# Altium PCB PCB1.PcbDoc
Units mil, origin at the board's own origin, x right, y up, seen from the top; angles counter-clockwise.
Board outline 2600 x 2600 mil, 2 copper layers (Top Layer, Bottom Layer); 21 components, 109 nets, 295 pads, 0 vias.
Unrouted connection lines stored in the file: 152.
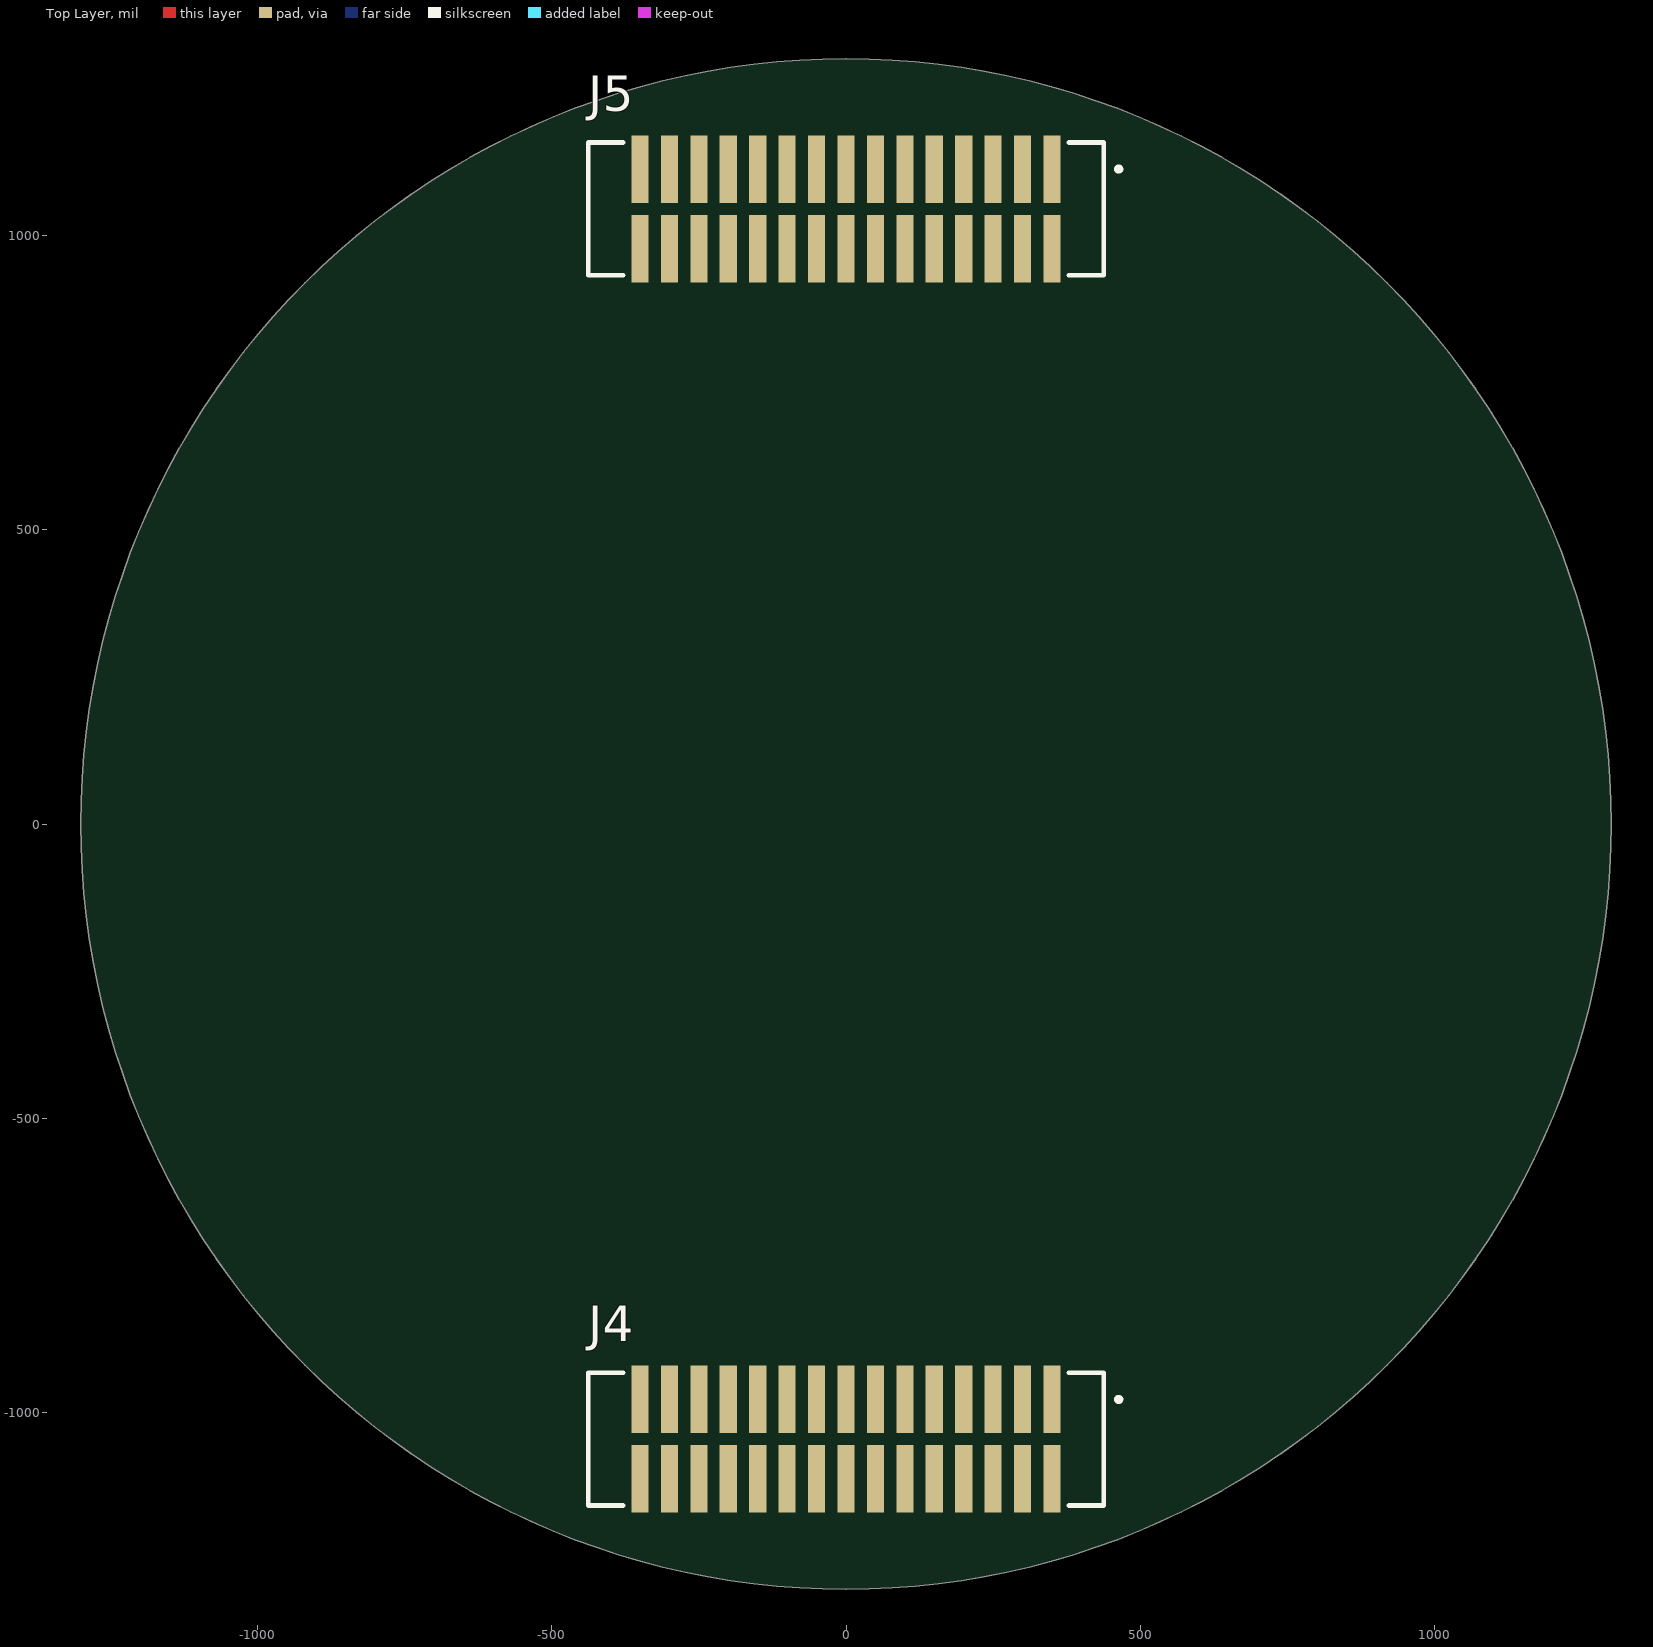
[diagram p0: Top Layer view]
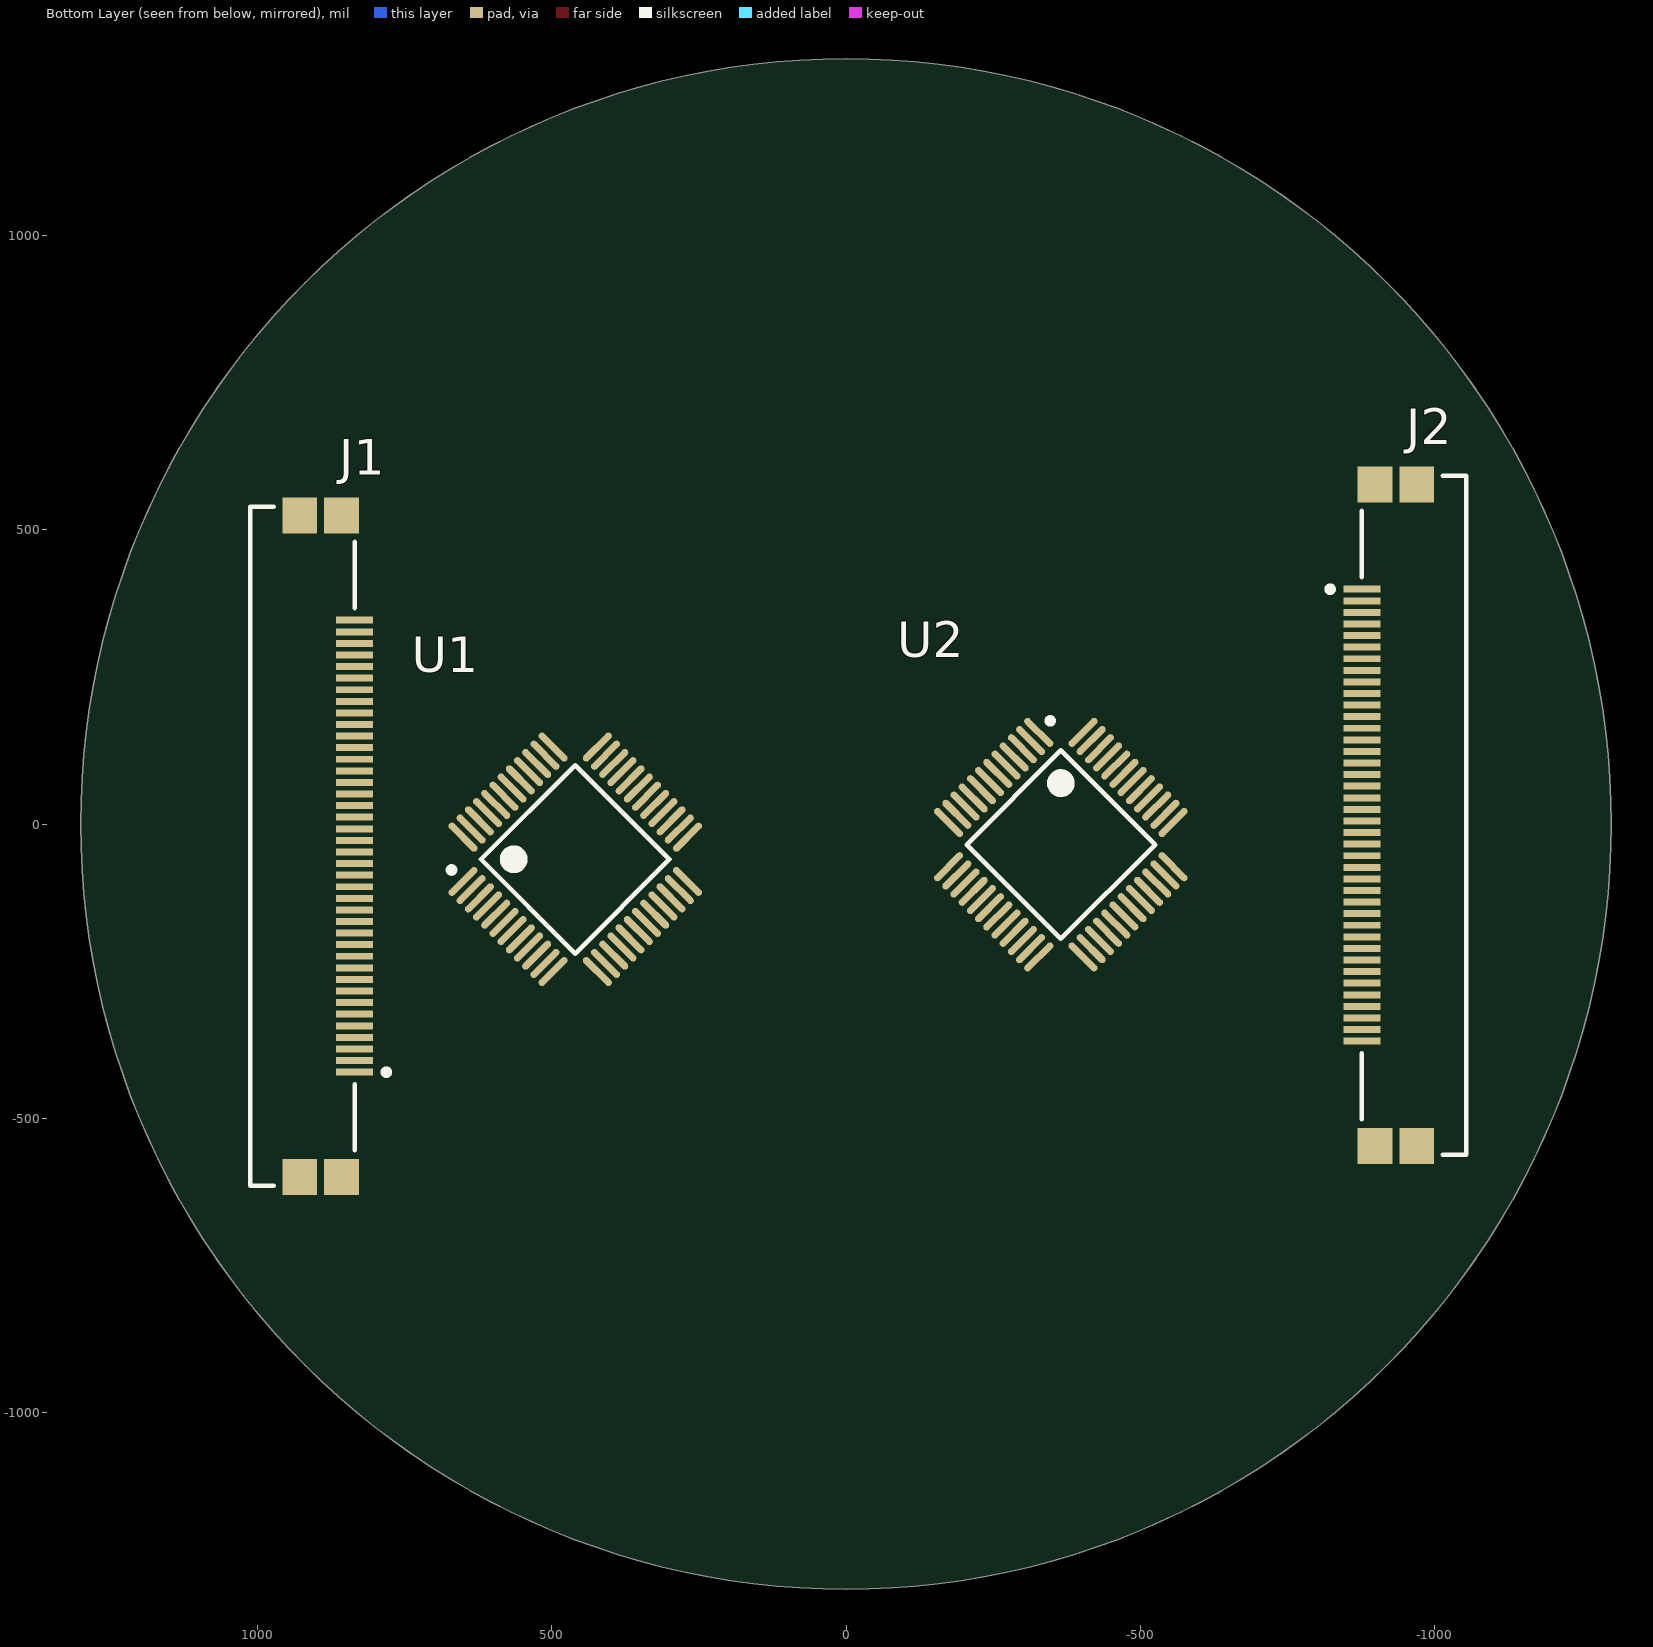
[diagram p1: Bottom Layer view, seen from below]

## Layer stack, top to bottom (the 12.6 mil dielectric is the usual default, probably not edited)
Top Solder: solder mask 0.4, Solder Resist, Dk 3.5
Top Layer: signal copper 1.4
Dielectric 1: dielectric 12.6, FR-4, Dk 4.8
Bottom Layer: signal copper 1.4
Bottom Solder: solder mask 0.4, Solder Resist, Dk 3.5

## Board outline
-1300,0 ccw(c0,0) 0,-1300 ccw(c0,0) 1300,0 ccw(c0,0) 0,1300 ccw(c0,0)

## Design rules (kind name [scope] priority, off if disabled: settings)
Clearance [All] p1: gap=8 ignorepadtopadclearanceinfootprint=FALSE except(6: Arc-SMDPad Track-SMDPad SMDPad-SMDPad; 12: Arc-Via Track-Via)
HoleSize [All] p1: absolutevalues=TRUE maxlimit=100 minlimit=14 maxpercent=80.000 minpercent=20.000
PolygonConnect [All] p1: connectstyle=Relief reliefconductorwidth=10 reliefentries=4 polygonreliefangle="90 Angle" airgapwidth=10
RoutingVias [All] p1: holewidth=14 width=28 viastyle="Through Hole" minholewidth=14 minwidth=28 maxholewidth=14 maxwidth=28
SolderMaskExpansion [All] p1: expansion=4 istentingtop=FALSE
Width [All] p1: maxlimit=30 minlimit=10 preferedwidth=10
29 further rules are at their usual default settings.

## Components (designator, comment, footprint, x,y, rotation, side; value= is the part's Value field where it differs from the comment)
C1 "330nF" FP-CC0805-0_85-MFG 4445,5125 r0 top value="330 nF"
C2 "33nF" CAPC2013X95X45NL10T25 4260,5135 r0 top
C3 "3.3nF" FP-C0805C-DN-MFG 4085,5125 r0 top value="3,300 pF"
C4 "330pF" FP-C0805C-DN-MFG 3915,5125 r0 top value="330 pF"
C5 "100 nF" FP-C0805C-DN-MFG 3575,5125 r0 top value="0.10 μF"
C6 "100 nF" FP-C0805C-DN-MFG 3035,5125 r0 top value="0.10 μF"
C7 "100 nF" FP-C0805C-DN-MFG 2865,5125 r0 top value="0.10 μF"
J1 "200485-0540" FP-200485-0540-MFG 923.39,-37.68 r270 bottom
J2 "200485-0540" FP-200485-0540-MFG -965,15 r90 bottom
J3 "5600200620" FP-5600200620-MFG 4820,5010 r90 top
J4 "TFM-115-02-L-D" SAMTEC_TFM-115-02-L-D 0,-1045 r180 top
J5 "TFM-115-02-L-D" SAMTEC_TFM-115-02-L-D 0,1045 r180 top
P1 "61300311021" 61300311021 1735,5020 r0 top
P2 "61300211021" 61300211021 2065,5020 r0 top
P3 "61300211021" 61300211021 2345,5020 r0 top
R1 "100" RESC2013X50X30LL20T20 5535,5140 r0 top
R2 "1k" RESC2013X55X40LL15T20 3740,5140 r0 top
S1 "SSSS212400" SSSS212400 2670,4675 r90 top
U1 "ADG732BSUZ-REEL" ADI-SU-48_N 460,-60 r135 bottom
U2 "ADG732BSUZ-REEL" ADI-SU-48_N -365,-35 r225 bottom
U3 "OPA2388IDR" FP-D0008A-IPC_B 3315,5060 r0 top

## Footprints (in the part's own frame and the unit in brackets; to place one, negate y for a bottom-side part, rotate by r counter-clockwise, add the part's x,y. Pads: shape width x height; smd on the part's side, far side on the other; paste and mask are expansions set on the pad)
61300211021 [mm] "Pin Header, pitch 2.54 mm, THT, Angled, single row, 2p"
  rect 1.65x1.65 hole 1.1: 1(1.27,2.77)
  round 1.65 hole 1.1: 2(-1.27,2.77)
  silkscreen extent -2.69,-7.27 2.69,1.35, body extent -2.54,-7.27 2.54,3.09, height 2.58
61300311021 [mm] "Pin Header, pitch 2.54 mm, THT, Angled, single row, 3p"
  rect 1.65x1.65 hole 1.1: 1(2.54,2.77)
  round 1.65 hole 1.1: 2(0,2.77) 3(-2.54,2.77)
  silkscreen extent -3.96,-7.27 3.96,1.35, body extent -3.81,-7.27 3.81,3.09, height 2.58
ADI-SU-48_N [mm] "QFP, 48-Leads, Body 7x7mm, Pitch 0.5mm, IPC Medium Density"
  oval 1.65x0.3 smd: 1(-4.1,2.75) 2(-4.1,2.25) 3(-4.1,1.75) 4(-4.1,1.25) 5(-4.1,0.75) 6(-4.1,0.25) 7(-4.1,-0.25) 8(-4.1,-0.75) 9(-4.1,-1.25) 10(-4.1,-1.75) 11(-4.1,-2.25) 12(-4.1,-2.75) 25(4.1,-2.75) 26(4.1,-2.25) 27(4.1,-1.75) 28(4.1,-1.25) 29(4.1,-0.75) 30(4.1,-0.25) 31(4.1,0.25) 32(4.1,0.75) 33(4.1,1.25) 34(4.1,1.75) 35(4.1,2.25) 36(4.1,2.75)
  oval 0.3x1.65 smd: 13(-2.75,-4.1) 14(-2.25,-4.1) 15(-1.75,-4.1) 16(-1.25,-4.1) 17(-0.75,-4.1) 18(-0.25,-4.1) 19(0.25,-4.1) 20(0.75,-4.1) 21(1.25,-4.1) 22(1.75,-4.1) 23(2.25,-4.1) 24(2.75,-4.1) 37(2.75,4.1) 38(2.25,4.1) 39(1.75,4.1) 40(1.25,4.1) 41(0.75,4.1) 42(0.25,4.1) 43(-0.25,4.1) 44(-0.75,4.1) 45(-1.25,4.1) 46(-1.75,4.1) 47(-2.25,4.1) 48(-2.75,4.1)
  silkscreen extent -4.22,-2.88 2.88,3.57, body extent -3.5,-3.5 3.5,3.5, height 1.2
CAPC2013X95X45NL10T25 [mm] "Chip Capacitor, 2-Leads, Body 2.00x1.25mm, IPC Medium Density"
  rect 1.2x1.4 smd: 1(-0.85,0) 2(0.85,0)
  body extent -1.05,-0.67 1.05,0.67, height 0.95
FP-200485-0540-MFG [mm]
  rect 0.3x1.6 smd paste-1000 mask+0: 1(9.75,2.245) 2(9.25,2.245) 3(8.75,2.245) 4(8.25,2.245) 5(7.75,2.245) 6(7.25,2.245) 7(6.75,2.245) 8(6.25,2.245) 9(5.75,2.245) 10(5.25,2.245) 11(4.75,2.245) 12(4.25,2.245) 13(3.75,2.245) 14(3.25,2.245) 15(2.75,2.245) 16(2.25,2.245) 17(1.75,2.245) 18(1.25,2.245) 19(0.75,2.245) 20(0.25,2.245) 21(-0.25,2.245) 22(-0.75,2.245) 23(-1.25,2.245) 24(-1.75,2.245) 25(-2.25,2.245) 26(-2.75,2.245) 27(-3.25,2.245) 28(-3.75,2.245) 29(-4.25,2.245) 30(-4.75,2.245) 31(-5.25,2.245) 32(-5.75,2.245) 33(-6.25,2.245) 34(-6.75,2.245) 35(-7.25,2.245) 36(-7.75,2.245) 37(-8.25,2.245) 38(-8.75,2.245) 39(-9.25,2.245) 40(-9.75,2.245)
  rect 1.55x1.5 smd paste+0 mask+0: 41(-14.275,1.685) 42(14.275,1.685) 43(-14.275,-0.115) 44(14.275,-0.115)
  silkscreen extent -14.65,-2.25 14.65,3.74, body extent -14.75,-2.2 14.74,2.8, height 5.7
FP-5600200620-MFG [mm]
  rect 1.2x2.2 smd paste+0 mask+0: 1(5,4.68) 2(3,4.68) 3(1,4.68) 4(-1,4.68) 5(-3,4.68) 6(-5,4.68)
  rect 2x4.2 smd paste+0 mask+0: 7(-8.6,-0.9) 8(8.6,-0.9)
  silkscreen extent -9.43,-4 9.43,6.63, body extent -9.7,-4.1 9.7,5.88, height 0.25
FP-C0805C-DN-MFG [mm]
  rect 0.95x1.35 smd paste+0 mask+0: 1(-0.75,0) 2(0.75,0)
  silkscreen extent -1.1,-1.07 1.1,1.07, body extent -1.4,-0.85 1.4,0.85, height 0.25
FP-CC0805-0_85-MFG [mm]
  rect 0.95x1.4 smd paste+0 mask+0: 1(-0.925,0) 2(0.925,0)
  silkscreen extent -0.08,-0.72 0.08,0.72, body extent -1.6,-1.05 1.6,1.05, height 0.25
FP-D0008A-IPC_B [mil]
  rect 85.4x22.92 smd paste+0 mask+0: 1(-93.06,75)
  rrect100% 85.4x22.92 smd paste+0 mask+0: 2(-93.06,25) 3(-93.06,-25) 4(-93.06,-75) 5(93.06,-75) 6(93.06,-25) 7(93.06,25) 8(93.06,75)
  silkscreen extent -162,-97 31,97, body extent -146,-106 146,106, height 10
RESC2013X50X30LL20T20 [mm] "Chip Resistor, 2-Leads, Body 2.00x1.25mm, IPC High Density"
  rect 0.85x1.35 smd: 1(-0.825,0) 2(0.825,0)
  silkscreen extent -0.1,-0.58 0.1,0.58, body extent -1.1,-0.72 1.1,0.72, height 0.5
RESC2013X55X40LL15T20 [mm] "Chip Resistor, 2-Leads, Body 2.00x1.25mm, IPC High Density"
  rect 0.9x1.3 smd: 1(-0.775,0) 2(0.775,0)
  body extent -1.07,-0.7 1.07,0.7, height 0.55
SAMTEC_TFM-115-02-L-D [mm]
  rect 0.74x2.92 smd: 01(-8.89,-1.715) 02(-8.89,1.715) 03(-7.62,-1.715) 04(-7.62,1.715) 05(-6.35,-1.715) 06(-6.35,1.715) 07(-5.08,-1.715) 08(-5.08,1.715) 09(-3.81,-1.715) 10(-3.81,1.715) 11(-2.54,-1.715) 12(-2.54,1.715) 13(-1.27,-1.715) 14(-1.27,1.715) 15(0,-1.715) 16(0,1.715) 17(1.27,-1.715) 18(1.27,1.715) 19(2.54,-1.715) 20(2.54,1.715) 21(3.81,-1.715) 22(3.81,1.715) 23(5.08,-1.715) 24(5.08,1.715) 25(6.35,-1.715) 26(6.35,1.715) 27(7.62,-1.715) 28(7.62,1.715) 29(8.89,-1.715) 30(8.89,1.715)
  silkscreen extent -11.87,-2.86 11.11,2.86, body extent -11.11,-3.05 11.11,2.92, height 5.71
SSSS212400 [mm]
  round 1.4 hole 0.9: 1(0,0) 2(2,0) 3(6,0) 4(8,0) 5(10,0) 6(0,3.3) 7(2,3.3) 8(6,3.3) 9(8,3.3) 10(10,3.3)
  silkscreen extent -2.5,-2.1 12.5,3.4, body extent -2.5,-2.1 12.5,3.65, height 3.6

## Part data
C1: library part CMP-03422-000882-1, "Surface Mount Ceramic Multilayer Capacitor 0.33uF 10% X7R 16V 0805 Blister T/R", Capacitance="330 nF", Manufacturer=Yageo, Manufacturer Part Number=CC0805KKX7R7BB334, Package=CC0805-0.85, Temperature="-30°C to +85°C", Temperature Characteristic=X7R, Temperature Range High=+85°C, Temperature Range Low=-30°C, Tolerance=0.1, Voltage Rating="16 V"
C2: library part CMP-1036-04169-2, Manufacturer=Murata, Part Number=GRM219R71H333KA01D
C3: library part CMP-2007-00373-2, "CAP CER 3300PF 50V X7R 0805", Capacitance="3,300 pF", Manufacturer=KEMET, Manufacturer Part Number=C0805C332K5RACTU, Package=C0805C-DN, Temperature="-55°C to +125°C", Temperature Characteristic=X7R, Temperature Coefficient=30ppm/°C, Temperature Range High=+125°C, Temperature Range Low=-55°C, Tolerance=0.1, Voltage Rating="50 V"
C4: library part CMP-2007-00598-2, "CAP CER 330PF 50V C0G/NP0 0805", Capacitance="330 pF", Manufacturer=KEMET, Manufacturer Part Number=C0805C331J5GACTU, Package=C0805C-DN, Temperature="-55°C to +125°C", Temperature Characteristic=C0G, Temperature Coefficient=30ppm/°C, Temperature Range High=+125°C, Temperature Range Low=-55°C, Tolerance=0.05, Voltage Rating="50 V"
C5 C6 C7: library part CMP-2007-00279-2, "CAP CER 0.1UF 50V X7R 0805", Capacitance="0.10 μF", Manufacturer=KEMET, Manufacturer Part Number=C0805C104K5RACTU, Package=C0805C-DN, Temperature="-55°C to +125°C", Temperature Characteristic=X7R, Temperature Coefficient=30ppm/°C, Temperature Range High=+125°C, Temperature Range Low=-55°C, Tolerance=0.1, Voltage Rating="50 V"
J1 J2: library part CMP-04775-000016-1, "0.5ONE-TOUCH ST 40P"
J3: library part CMP-04776-000066-1, "CONN HEADER SMD 6POS 2MM", Current Rating=3A, Manufacturer=Molex, Temperature="-40°C to +125°C", Temperature Range High=+125°C, Temperature Range Low=-40°C, Voltage Rating=125V
J4 J5: Package=None
P1: library part CMP-1502-01061-1, "THT Angled Pin Header WR-PHD, Pitch 2.54 mm, Single Row, 3 pins", Contact Resistance=20mOhm, Manufacturer="Wurth Elektronik", Operating Temperature=-40to105degC, Rated Current=3A, Withstanding Voltage=500VAC, Working Voltage=250VAC
P2 P3: library part CMP-1502-01059-1, "THT Angled Pin Header WR-PHD, Pitch 2.54 mm, Single Row, 2 pins", Contact Resistance=20mOhm, Manufacturer="Wurth Elektronik", Operating Temperature=-40to105degC, Rated Current=3A, Withstanding Voltage=500VAC, Working Voltage=250VAC
R1: library part CMP-2001-04901-1, Manufacturer="Vishay Dale", Part Number=CRCW0805100RFKEA
R2: library part CMP-2001-04738-1, "TNPW08051K00BEEN", Manufacturer="Vishay Dale"
S1: "Switch", Manufacturer_Name="ALPS Electric", Mouser Part Number=688-SSSS212400
U1 U2: library part CMP-0798-00236-1, "1.8 to 5.5 V / +/-2.5 V, 4 Ohm, 32-Channel Analog Multiplexer, -40 to 85 degC, 48-pin QFP (SU-48), Reel", Manufacturer="Analog Devices"
U3: library part CMP-04895-000483-1, "IC OPAMP ZER-DRIFT 2CIRC 8SOIC", Max Operating Temperature=125°C, Min Operating Temperature=-40°C

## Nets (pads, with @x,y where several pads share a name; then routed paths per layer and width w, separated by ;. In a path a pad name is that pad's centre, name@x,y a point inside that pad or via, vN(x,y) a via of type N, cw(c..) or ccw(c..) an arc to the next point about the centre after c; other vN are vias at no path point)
1V_REF: J5.05 U3.3
2V_REF: J5.06
3.3V: C5.2 U3.8
3V3: C6.1 C7.1 J3.1 J5.03 J5.04 U1.13 U1.14 U2.13 U2.14
5KHZ_POLE: C2.2 S1.9
50KHZ_POLE: C3.2 S1.7
500HZ_POLE: C1.2 S1.10
500KHZ_POLE: C4.1 S1.6
!ADC_CS: J5.21
!BME_CS: J3.6 J5.29
!CHIP_EN: J4.19 U1.22 U2.22
!DAC_CS: J5.23
!GATE_SHDN: J5.28
+11V: J4.13
-11V: J4.14
DRAIN_SEL0: J4.22 U1.15
DRAIN_SEL1: J5.17 U1.16
DRAIN_SEL2: J4.24 U1.17
DRAIN_SEL3: J5.15 U1.18
DRAIN_SEL4: J5.18 U1.19
GATE1: J1.1 J4.04 P1.1
GATE2: J1.2 J4.06 P1.2
GATE3: J1.3 J4.03 P1.3
GATE4: J4.05
GATE5: J4.10
GATE6: J4.09
GATE_AMP: J4.21
GND: C5.1 C6.2 C7.2 J3.2 J4.01 J4.02 J4.07 J4.08 J4.11 J4.12 J4.15 J4.16 J4.20 J4.23 J4.28 J5.01 J5.02 J5.07 J5.08 J5.11 J5.13 J5.14 J5.16 J5.19 J5.24 J5.27 U1.20 U1.21 U1.23 U1.24 U2.20 U2.21 U2.23 U2.24 U3.4
GPIO13: J4.18
HEAT_THERM_BUFF: J4.25
IDS: C1.1 C2.1 C3.1 C4.2 R2.1 U2.43 U3.2
IDS1: J2.4 P2.1 U2.12
IDS2: J2.5 U2.11
IDS3: J2.6 U2.10
IDS4: J2.7 U2.9
IDS5: J2.8 U2.8
IDS6: J2.9 U2.7
IDS7: J2.10 U2.6
IDS8: J2.11 U2.5
IDS9: J2.12 U2.4
IDS10: J2.13 U2.3
IDS11: J2.14 U2.2
IDS12: J2.15 U2.1
IDS13: J2.16 U2.48
IDS14: J2.17 U2.47
IDS15: J2.18 U2.46
IDS16: J2.19 U2.45
IDS17: J2.35 U2.25
IDS18: J2.34 U2.26
IDS19: J2.33 U2.27
IDS20: J2.32 U2.28
IDS21: J2.31 U2.29
IDS22: J2.30 U2.30
IDS23: J2.29 U2.31
IDS24: J2.28 U2.32
IDS25: J2.27 U2.33
IDS26: J2.26 U2.34
IDS27: J2.25 U2.35
IDS28: J2.24 U2.36
IDS29: J2.23 U2.37
IDS30: J2.22 U2.38
IDS31: J2.21 U2.39
IDS32: J2.20 P2.2 U2.40
LOW_BATT: J4.29
MISO: J5.22 R1.2
MOSI: J3.5 J5.30
NetJ3_4: J3.4 R1.1
SCAN: J4.27
SCK: J3.3 J5.20
SOURCE_SEL0: J5.26 U2.15
SOURCE_SEL1: J5.25 U2.16
SOURCE_SEL2: J4.17 U2.17
SOURCE_SEL3: J4.30 U2.18
SOURCE_SEL4: J4.26 U2.19
VDS1: J1.4 P3.1 U1.12
VDS2: J1.5 U1.11
VDS3: J1.6 U1.10
VDS4: J1.7 U1.9
VDS5: J1.8 U1.8
VDS6: J1.9 U1.7
VDS7: J1.10 U1.6
VDS8: J1.11 U1.5
VDS9: J1.12 U1.4
VDS10: J1.13 U1.3
VDS11: J1.14 U1.2
VDS12: J1.15 U1.1
VDS13: J1.16 U1.48
VDS14: J1.17 U1.47
VDS15: J1.18 U1.46
VDS16: J1.19 U1.45
VDS17: J1.35 U1.25
VDS18: J1.34 U1.26
VDS19: J1.33 U1.27
VDS20: J1.32 U1.28
VDS21: J1.31 U1.29
VDS22: J1.30 U1.30
VDS23: J1.29 U1.31
VDS24: J1.28 U1.32
VDS25: J1.27 U1.33
VDS26: J1.26 U1.34
VDS27: J1.25 U1.35
VDS28: J1.24 U1.36
VDS29: J1.23 U1.37
VDS30: J1.22 U1.38
VDS31: J1.21 U1.39
VDS32: J1.20 P3.2 U1.40
VDS_BUFF: J5.09 U1.43 U3.6 U3.7
VDS_RAW: J5.10 U3.5
VMEAS: J5.12 R2.2 S1.8 U3.1
pads on no net: J1.36 J1.37 J1.38 J1.39 J1.40 J1.41 J1.42 J1.43 J1.44 J2.1 J2.2 J2.3 J2.36 J2.37 J2.38 J2.39 J2.40 J2.41 J2.42 J2.43 J2.44 J3.7 J3.8 S1.1 S1.2 S1.3 S1.4 S1.5 U1.41 U1.42 U1.44 U2.41 U2.42 U2.44

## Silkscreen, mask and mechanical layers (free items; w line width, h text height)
Mechanical 1:
  circle w5: c0,0 r1300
